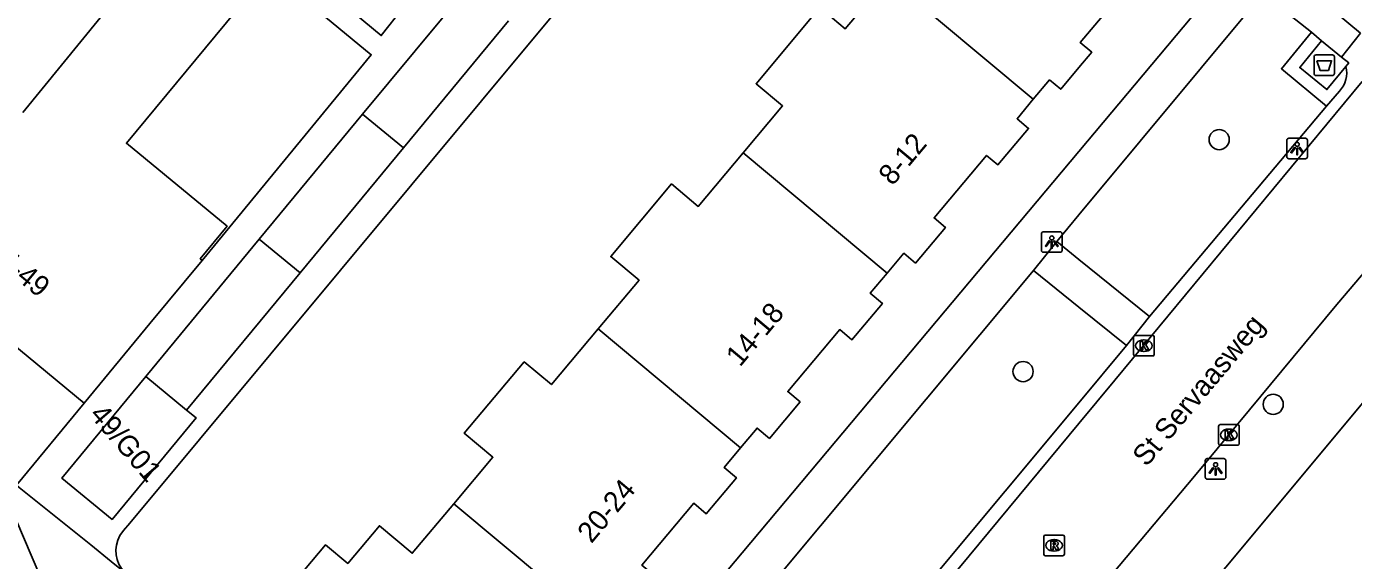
# Model space of a CAD drawing. Extents: x 162074 to 163034, y 381824 to 382557.
# Drawn here: x 162449 to 162513.3, y 382070.3 to 382096.2 of the extents above; entities that cross this region are included whole.
import ezdxf

# ---------------------------------------------------------------- set-up
doc = ezdxf.new("R2010")
doc.units = 0
for name, color, linetype in [('IMGEO_Afval_apart_plaats', 7, 'Continuous'), ('IMGEO_Boom', 7, 'Continuous'), ('IMGEO_Kolk', 7, 'Continuous'), ('IMGEO_Lichtpunt', 7, 'Continuous'), ('IMGEO_Openbare_ruimte_label', 7, 'Continuous'), ('IMGEO_Pand', 7, 'Continuous'), ('IMGEO_Pand_nummerreeks', 7, 'Continuous'), ('IMGEO_Rijbaan_lokaal_open', 7, 'Continuous'), ('IMGEO_Rioolput', 7, 'Continuous'), ('IMGEO_Voetpad_gesloten', 7, 'Continuous'), ('IMGEO_Voetpad_open', 7, 'Continuous')]:
    doc.layers.add(name, color=color, linetype=linetype)

msp = doc.modelspace()

# ---------------------------------------------------------------- linework, layer by layer
at = {"layer": 'IMGEO_Afval_apart_plaats'}
for p, q in [((162511.394, 382093.965), (162511.394, 382094.765)), ((162511.394, 382094.765), (162511.394, 382093.965)), ((162511.494, 382094.865), (162512.284, 382094.865)), ((162512.284, 382094.865), (162511.494, 382094.865)), ((162512.384, 382094.765), (162512.384, 382093.965)), ((162512.384, 382093.965), (162512.384, 382094.765)), ((162512.284, 382093.865), (162511.494, 382093.865)), ((162511.494, 382093.865), (162512.284, 382093.865))]:
    msp.add_line(p, q, dxfattribs=at)
msp.add_lwpolyline([(162511.537, 382094.579), (162512.241, 382094.579), (162512.092, 382094.109), (162511.686, 382094.109), (162511.537, 382094.579)], dxfattribs=at)
for centre, start, end in [((162511.494, 382094.765), 90, 180), ((162511.494, 382094.765), 90, 180), ((162512.284, 382094.765), 0, 90), ((162512.284, 382094.765), 360, 90), ((162511.494, 382093.965), 180, 270), ((162511.494, 382093.965), 180, 270), ((162512.284, 382093.965), 270, 0), ((162512.284, 382093.965), 270, 0)]:
    msp.add_arc(centre, 0.1, start, end, dxfattribs=at)
at = {"layer": 'IMGEO_Boom'}
for centre in [(162506.8, 382090.755), (162497.301, 382079.503), (162509.418, 382077.916)]:
    msp.add_circle(centre, 0.489, dxfattribs=at)
at = {"layer": 'IMGEO_Kolk'}
for p, q in [((162502.653, 382080.335), (162502.653, 382081.187)), ((162502.728, 382081.261), (162503.58, 382081.261)), ((162503.654, 382081.187), (162503.654, 382080.335)), ((162503.164, 382080.481), (162503.139, 382080.481)), ((162503.141, 382081.041), (162503.166, 382081.041)), ((162503.58, 382080.261), (162502.728, 382080.261)), ((162506.769, 382076.01), (162506.769, 382076.862)), ((162506.844, 382076.936), (162507.696, 382076.936)), ((162507.257, 382076.716), (162507.282, 382076.716)), ((162507.77, 382076.862), (162507.77, 382076.01)), ((162507.28, 382076.156), (162507.255, 382076.156)), ((162507.696, 382075.936), (162506.844, 382075.936))]:
    msp.add_line(p, q, dxfattribs=at)
for points in [[(162502.653, 382080.335), (162502.653, 382081.187)], [(162502.728, 382081.261), (162503.58, 382081.261)], [(162503.654, 382081.187), (162503.654, 382080.335)], [(162502.974, 382080.961), (162503.097, 382080.961), (162503.097, 382080.81), (162503.227, 382080.961), (162503.391, 382080.961), (162503.245, 382080.81), (162503.398, 382080.561), (162503.246, 382080.561), (162503.161, 382080.725), (162503.097, 382080.658), (162503.097, 382080.561), (162502.974, 382080.561), (162502.974, 382080.961)], [(162503.58, 382080.261), (162502.728, 382080.261)], [(162506.769, 382076.01), (162506.769, 382076.862)], [(162506.844, 382076.936), (162507.696, 382076.936)], [(162507.09, 382076.636), (162507.213, 382076.636), (162507.213, 382076.485), (162507.343, 382076.636), (162507.507, 382076.636), (162507.361, 382076.485), (162507.514, 382076.236), (162507.362, 382076.236), (162507.277, 382076.4), (162507.213, 382076.333), (162507.213, 382076.236), (162507.09, 382076.236), (162507.09, 382076.636)], [(162507.77, 382076.862), (162507.77, 382076.01)], [(162507.696, 382075.936), (162506.844, 382075.936)]]:
    msp.add_lwpolyline(points, dxfattribs=at)
for centre, start, end in [((162502.73, 382081.185), 91.55205, 178.44795), ((162502.73, 382081.185), 91.55205, 178.44795), ((162503.578, 382081.185), 1.55205, 88.44795), ((162503.578, 382081.185), 1.55205, 88.44795), ((162502.73, 382080.337), 181.55205, 268.44795), ((162502.73, 382080.337), 181.55205, 268.44795), ((162503.578, 382080.337), 271.55205, 358.44795), ((162503.578, 382080.337), 271.55205, 358.44795), ((162506.846, 382076.86), 91.55205, 178.44795), ((162506.846, 382076.86), 91.55205, 178.44795), ((162507.694, 382076.86), 1.55205, 88.44795), ((162507.694, 382076.86), 1.55205, 88.44795), ((162506.846, 382076.012), 181.55205, 268.44795), ((162506.846, 382076.012), 181.55205, 268.44795), ((162507.694, 382076.012), 271.55205, 358.44795), ((162507.694, 382076.012), 271.55205, 358.44795)]:
    msp.add_arc(centre, 0.0765, start, end, dxfattribs=at)
for centre, major_axis, ratio, start_param, end_param in [((162503.14, 382080.761), (-0.387, 0.002), 0.722429, 4.712389, 7.853982), ((162503.165, 382080.761), (-0.39, 0.002), 0.717154, 1.570796, 4.712389), ((162507.256, 382076.436), (-0.387, 0.002), 0.722429, 4.712389, 7.853982), ((162507.281, 382076.436), (-0.39, 0.002), 0.717154, 1.570796, 4.712389)]:
    msp.add_ellipse(centre, major_axis=major_axis, ratio=ratio, start_param=start_param, end_param=end_param, dxfattribs=at)
at = {"layer": 'IMGEO_Lichtpunt'}
for p, q in [((162510.98, 382090.821), (162510.172, 382090.821)), ((162510.98, 382090.821), (162510.172, 382090.821)), ((162510.078, 382090.726), (162510.078, 382089.919)), ((162510.078, 382090.726), (162510.078, 382089.919)), ((162511.074, 382089.919), (162511.074, 382090.726)), ((162511.074, 382089.919), (162511.074, 382090.726)), ((162510.172, 382089.825), (162510.98, 382089.825)), ((162510.172, 382089.825), (162510.98, 382089.825)), ((162499.096, 382086.286), (162498.288, 382086.286)), ((162499.096, 382086.286), (162498.288, 382086.286)), ((162498.194, 382086.191), (162498.194, 382085.384)), ((162498.194, 382086.191), (162498.194, 382085.384)), ((162499.19, 382085.384), (162499.19, 382086.191)), ((162499.19, 382085.384), (162499.19, 382086.191)), ((162498.288, 382085.29), (162499.096, 382085.29)), ((162498.288, 382085.29), (162499.096, 382085.29)), ((162506.126, 382075.188), (162506.126, 382074.381)), ((162506.126, 382075.188), (162506.126, 382074.381)), ((162507.028, 382075.283), (162506.22, 382075.283)), ((162507.028, 382075.283), (162506.22, 382075.283)), ((162507.122, 382074.381), (162507.122, 382075.188)), ((162507.122, 382074.381), (162507.122, 382075.188)), ((162506.22, 382074.287), (162507.028, 382074.287)), ((162506.22, 382074.287), (162507.028, 382074.287))]:
    msp.add_line(p, q, dxfattribs=at)
for points in [[(162510.452, 382090.39), (162510.491, 382090.362), (162510.303, 382090.1), (162510.265, 382090.127), (162510.452, 382090.39)], [(162510.554, 382090.342), (162510.601, 382090.342), (162510.601, 382090.02), (162510.554, 382090.02), (162510.554, 382090.342)], [(162510.664, 382090.362), (162510.702, 382090.389), (162510.889, 382090.127), (162510.85, 382090.099), (162510.664, 382090.362)], [(162498.568, 382085.855), (162498.607, 382085.827), (162498.419, 382085.565), (162498.381, 382085.592), (162498.568, 382085.855)], [(162498.67, 382085.807), (162498.717, 382085.807), (162498.717, 382085.485), (162498.67, 382085.485), (162498.67, 382085.807)], [(162498.78, 382085.827), (162498.818, 382085.854), (162499.005, 382085.592), (162498.966, 382085.564), (162498.78, 382085.827)], [(162506.5, 382074.852), (162506.539, 382074.824), (162506.351, 382074.562), (162506.313, 382074.589), (162506.5, 382074.852)], [(162506.602, 382074.804), (162506.649, 382074.804), (162506.649, 382074.482), (162506.602, 382074.482), (162506.602, 382074.804)], [(162506.712, 382074.824), (162506.75, 382074.851), (162506.937, 382074.589), (162506.898, 382074.561), (162506.712, 382074.824)]]:
    msp.add_lwpolyline(points, dxfattribs=at)
for centre in [(162510.577, 382090.524), (162498.693, 382085.989), (162506.625, 382074.986)]:
    msp.add_circle(centre, 0.0994, dxfattribs=at)
for centre, start, end in [((162510.172, 382090.726), 90, 180), ((162510.172, 382090.726), 90, 180), ((162510.98, 382090.726), 0, 90), ((162510.98, 382090.726), 0, 90), ((162510.172, 382089.919), 180, 270), ((162510.172, 382089.919), 180, 270), ((162510.98, 382089.919), 270, 0), ((162510.98, 382089.919), 270, 360), ((162498.288, 382086.191), 90, 180), ((162498.288, 382086.191), 90, 180), ((162499.096, 382086.191), 0, 90), ((162499.096, 382086.191), 0, 90), ((162498.288, 382085.384), 180, 270), ((162498.288, 382085.384), 180, 270), ((162499.096, 382085.384), 270, 0), ((162499.096, 382085.384), 270, 360), ((162506.22, 382075.188), 90, 180), ((162506.22, 382075.188), 90, 180), ((162507.028, 382075.188), 0, 90), ((162507.028, 382075.188), 0, 90), ((162506.22, 382074.381), 180, 270), ((162506.22, 382074.381), 180, 270), ((162507.028, 382074.381), 270, 0), ((162507.028, 382074.381), 270, 360)]:
    msp.add_arc(centre, 0.0946, start, end, dxfattribs=at)
at = {"layer": 'IMGEO_Pand'}
for points in [[(162457.641, 382102.913), (162466.216, 382095.799), (162467.266, 382097.134)], [(162457.546, 382084.897), (162457.449, 382084.977), (162458.753, 382086.556), (162453.876, 382090.581), (162460.128, 382098.157), (162456.35, 382101.275), (162448.864, 382092.063)], [(162497.798, 382092.71), (162498.587, 382093.651), (162499.124, 382093.201), (162500, 382094.245), (162500.628, 382094.994), (162500.07, 382095.462), (162502.548, 382098.417), (162503.115, 382097.942), (162504.623, 382099.74), (162504.044, 382100.225), (162504.837, 382101.171)], [(162483.743, 382090.108), (162485.653, 382092.386), (162484.368, 382093.463), (162487.463, 382097.156), (162488.689, 382096.129), (162490.761, 382098.6)], [(162497.798, 382092.71), (162490.761, 382098.6)], [(162465.311, 382091.983), (162470.406, 382098.153)], [(162472.384, 382096.524), (162467.289, 382090.354)], [(162490.714, 382084.273), (162491.527, 382085.242), (162492.092, 382084.769), (162493.543, 382086.499), (162492.995, 382086.959), (162495.537, 382089.991), (162496.084, 382089.533), (162497.567, 382091.302), (162497.01, 382091.769), (162497.798, 382092.71)], [(162460.311, 382085.928), (162465.311, 382091.983)], [(162467.289, 382090.354), (162465.311, 382091.983)], [(162467.289, 382090.354), (162462.29, 382084.299)], [(162476.729, 382081.582), (162478.702, 382083.936), (162477.331, 382085.086), (162480.279, 382088.603), (162481.572, 382087.519), (162483.743, 382090.108)], [(162483.743, 382090.108), (162490.714, 382084.273)], [(162454.815, 382079.272), (162460.311, 382085.928)], [(162460.311, 382085.928), (162462.29, 382084.299)], [(162451.833, 382077.976), (162443.204, 382085.098)], [(162457.546, 382084.897), (162455.016, 382081.832), (162451.833, 382077.976)], [(162462.29, 382084.299), (162456.791, 382077.64)], [(162483.622, 382075.812), (162484.42, 382076.764), (162485.019, 382076.261), (162486.506, 382078.034), (162485.908, 382078.535), (162488.425, 382081.538), (162489.01, 382081.048), (162490.491, 382082.815), (162489.904, 382083.306), (162490.714, 382084.273)], [(162469.733, 382073.093), (162471.622, 382075.346), (162470.233, 382076.51), (162473.139, 382079.977), (162474.458, 382078.872), (162476.729, 382081.582)], [(162483.622, 382075.812), (162476.729, 382081.582)], [(162454.815, 382079.272), (162450.745, 382074.342), (162453.176, 382072.336), (162457.245, 382077.265), (162456.791, 382077.64)], [(162456.791, 382077.64), (162454.815, 382079.272)], [(162476.559, 382067.379), (162477.347, 382068.319), (162477.918, 382067.84), (162479.415, 382069.627), (162478.832, 382070.116), (162481.349, 382073.119), (162481.958, 382072.609), (162483.422, 382074.356), (162482.823, 382074.858), (162483.622, 382075.812)], [(162462.616, 382064.462), (162459.875, 382066.76), (162463.519, 382071.107), (162464.597, 382070.203), (162466.126, 382072.027), (162467.72, 382070.691), (162469.733, 382073.093)], [(162469.733, 382073.093), (162476.559, 382067.379)]]:
    msp.add_lwpolyline(points, dxfattribs=at)
at = {"layer": 'IMGEO_Rijbaan_lokaal_open'}
for points in [[(162374.57, 382130.393), (162375.036, 382129.973), (162382.822, 382127.114), (162448.153, 382073.217), (162450.473, 382067.754), (162451.851, 382066.605)], [(162479.464, 382052.271), (162479.798, 382052.676), (162484.791, 382058.741), (162493.199, 382068.777), (162500, 382076.984), (162501.747, 382079.092), (162513.725, 382093.577)], [(162518.359, 382089.726), (162517.901, 382089.135), (162512.501, 382082.754), (162505.608, 382074.431), (162500, 382067.76), (162494.638, 382061.372), (162484.385, 382049.064), (162483.608, 382048.102)]]:
    msp.add_lwpolyline(points, dxfattribs=at)
at = {"layer": 'IMGEO_Rioolput'}
for p, q in [((162498.304, 382070.649), (162498.304, 382071.501)), ((162498.379, 382071.575), (162499.231, 382071.575)), ((162499.305, 382071.501), (162499.305, 382070.649)), ((162498.792, 382071.355), (162498.817, 382071.355)), ((162499.231, 382070.575), (162498.379, 382070.575)), ((162498.815, 382070.795), (162498.79, 382070.795))]:
    msp.add_line(p, q, dxfattribs=at)
for points in [[(162498.304, 382070.649), (162498.304, 382071.501)], [(162498.379, 382071.575), (162499.231, 382071.575)], [(162499.305, 382071.501), (162499.305, 382070.649)], [(162498.893, 382071.273), (162498.641, 382071.275), (162498.641, 382070.875)], [(162498.641, 382070.875), (162498.765, 382070.875), (162498.765, 382071.037), (162498.776, 382071.037)], [(162498.819, 382071.194), (162498.765, 382071.194), (162498.765, 382071.113)], [(162498.765, 382071.113), (162498.817, 382071.113)], [(162498.823, 382071.008), (162498.894, 382070.875), (162499.034, 382070.875), (162498.969, 382071.001)], [(162499.231, 382070.575), (162498.379, 382070.575)]]:
    msp.add_lwpolyline(points, dxfattribs=at)
for centre, radius, start, end in [((162498.381, 382071.499), 0.0765, 91.55205, 178.44795), ((162498.381, 382071.499), 0.0765, 91.55205, 178.44795), ((162499.229, 382071.499), 0.0765, 1.55205, 88.44795), ((162499.229, 382071.499), 0.0765, 1.55205, 88.44795), ((162498.775, 382070.984), 0.0533, 26.02933, 88.69889), ((162498.801, 382071.302), 0.19, 274.7715, 282.96867), ((162498.825, 382071.098), 0.0964, 77.00612, 93.18647), ((162498.839, 382071.155), 0.0378, 276.66336, 79.67722), ((162498.892, 382071.163), 0.109, 350.36119, 89.41601), ((162498.89, 382071.163), 0.112, 277.58423, 350.98172), ((162498.874, 382070.948), 0.108, 29.51342, 73.79051), ((162498.381, 382070.651), 0.0765, 181.55205, 268.44795), ((162498.381, 382070.651), 0.0765, 181.55205, 268.44795), ((162499.229, 382070.651), 0.0765, 271.55205, 358.44795), ((162499.229, 382070.651), 0.0765, 271.55205, 358.44795)]:
    msp.add_arc(centre, radius, start, end, dxfattribs=at)
for centre, major_axis, ratio, start_param, end_param in [((162498.791, 382071.075), (-0.387, 0.002), 0.722429, 4.712389, 7.853982), ((162498.816, 382071.075), (-0.39, 0.002), 0.717154, 1.570796, 4.712389)]:
    msp.add_ellipse(centre, major_axis=major_axis, ratio=ratio, start_param=start_param, end_param=end_param, dxfattribs=at)
at = {"layer": 'IMGEO_Voetpad_gesloten'}
for points in [[(162512.939, 382094.306), (162512.018, 382093.178), (162510.701, 382094.252), (162511.761, 382095.551)], [(162511.761, 382095.551), (162512.728, 382094.762)], [(162512.728, 382094.762), (162513.078, 382094.477), (162512.939, 382094.306)]]:
    msp.add_lwpolyline(points, dxfattribs=at)
at = {"layer": 'IMGEO_Voetpad_open'}
for points in [[(162389.437, 382141.114), (162397.649, 382151.094), (162465.734, 382094.868), (162457.546, 382084.897)], [(162488.112, 382113.139), (162454.033, 382072.15), (162453.74, 382071.792), (162453.561, 382071.549)], [(162513.64, 382095.914), (162508.44, 382100.255)], [(162507.419, 382099.039), (162500, 382090.184), (162471.924, 382056.673)], [(162498.931, 382085.813), (162500, 382087.1), (162508.922, 382097.842), (162511.276, 382095.959)], [(162511.276, 382095.959), (162509.817, 382094.19), (162512, 382092.37)], [(162511.761, 382095.551), (162511.276, 382095.959)], [(162513.64, 382095.914), (162512.728, 382094.762)], [(162512.623, 382093.111), (162512, 382092.37)], [(162512, 382092.37), (162503.429, 382082.174)], [(162485.32, 382043.802), (162495.527, 382056.09), (162500, 382061.465), (162521.435, 382087.22)], [(162498.931, 382085.813), (162497.815, 382084.401)], [(162503.429, 382082.174), (162500, 382084.948), (162498.931, 382085.813)], [(162484.884, 382068.897), (162497.815, 382084.401)], [(162497.815, 382084.401), (162500, 382082.633), (162502.313, 382080.762)], [(162503.429, 382082.174), (162502.313, 382080.762)], [(162502.313, 382080.762), (162500, 382077.988), (162489.372, 382065.239)], [(162448.544, 382073.992), (162451.833, 382077.976)], [(162453.791, 382069.764), (162453.132, 382070.292), (162452.152, 382071.11), (162448.681, 382073.879), (162448.544, 382073.992)]]:
    msp.add_lwpolyline(points, dxfattribs=at)
for centre, radius, start, end in [((162511.715, 382093.99), 1.264, 315.91184, 14.4642), ((162454.832, 382070.805), 1.472, 149.66197, 225.02242)]:
    msp.add_arc(centre, radius, start, end, dxfattribs=at)

# ---------------------------------------------------------------- texts
at = {"layer": 'IMGEO_Openbare_ruimte_label'}
msp.add_text('St Servaasweg', height=1, rotation=49.98904, dxfattribs=at).set_placement((162503.279, 382074.846))
at = {"layer": 'IMGEO_Pand_nummerreeks'}
for s, rotation, p in [('8-12', 50.02385, (162490.98, 382088.478)), ('45-49', 320.46591, (162447.002, 382085.231)), ('14-18', 50.03155, (162483.591, 382079.693)), ('49/G01', 310.59958, (162452.045, 382077.39)), ('20-24', 50.03155, (162476.395, 382071.132))]:
    msp.add_text(s, height=1, rotation=rotation, dxfattribs=at).set_placement(p)

doc.saveas('drawing.dxf')
